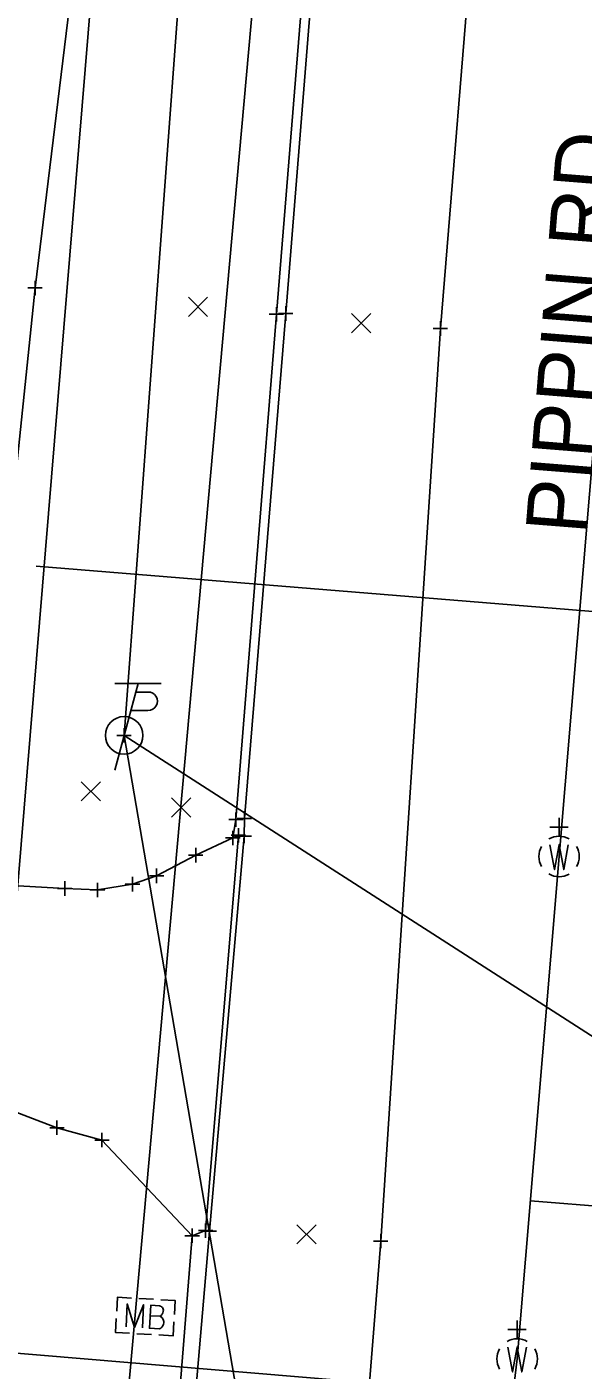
# Model space of a CAD drawing. Extents: x 1380440 to 1381945, y 468756 to 470369.
# Drawn here: x 1381508.5 to 1381547.1, y 469159.2 to 469252.2 of the extents above; entities that cross this region are included whole.
import ezdxf

# ---------------------------------------------------------------- set-up
doc = ezdxf.new("R2010")
doc.units = 0
for name, color, linetype in [('DR_X_Cells', 7, 'Continuous'), ('GE_P_Driveway_CL', 7, 'Continuous'), ('PM_X_CL_Double_Solid', 7, 'Continuous'), ('PV_X_COP', 7, 'Continuous'), ('RD_P_Cells', 7, 'Continuous'), ('RW_P_Const_Limits', 7, 'Continuous'), ('RW_P_Esmt_TMP', 7, 'Continuous'), ('RW_X_Esmt_SH', 7, 'Continuous'), ('SC_Scratch2', 7, 'Continuous'), ('SC_Shading1', 7, 'Continuous'), ('SH_Named_Boundary', 7, 'Continuous'), ('UT_X_Gas', 7, 'Continuous'), ('UT_X_Overhead_Combined', 7, 'Continuous'), ('UT_X_Sanitary_Line', 7, 'Continuous'), ('UT_X_Water', 7, 'Continuous'), ('X-CL', 7, 'Continuous'), ('X-SUBDIVISION', 7, 'Continuous')]:
    doc.layers.add(name, color=color, linetype=linetype)

msp = doc.modelspace()

# ---------------------------------------------------------------- linework, layer by layer
at = {"layer": 'DR_X_Cells'}
msp.add_lwpolyline([(1381528.617, 469268.06), (1381528.681, 469267.335), (1381525.826, 469232.259), (1381523.028, 469197.272), (1381522.806, 469196.001)], dxfattribs=at)
at = {"layer": 'GE_P_Driveway_CL'}
for p, q in [((1381519.728, 469232.108), (1381521.062, 469233.443)), ((1381519.728, 469233.443), (1381521.062, 469232.108)), ((1381531.026, 469230.976), (1381532.36, 469232.31)), ((1381531.026, 469232.31), (1381532.36, 469230.976)), ((1381512.301, 469198.557), (1381513.635, 469199.892)), ((1381512.301, 469199.892), (1381513.635, 469198.557)), ((1381518.558, 469197.448), (1381519.892, 469198.783)), ((1381518.558, 469198.783), (1381519.892, 469197.448)), ((1381527.245, 469167.888), (1381528.579, 469169.223)), ((1381527.245, 469169.223), (1381528.579, 469167.888))]:
    msp.add_line(p, q, dxfattribs=at)
at = {"layer": 'PM_X_CL_Double_Solid'}
msp.add_lwpolyline([(1381555.385, 469442.034), (1381550.974, 469391.016), (1381547.282, 469345.901), (1381541.953, 469289.547), (1381537.187, 469231.269), (1381533.052, 469168.087), (1381530.317, 469133.741), (1381523.968, 469065.081), (1381520.119, 469021.37), (1381518.183, 469001.306)], dxfattribs=at)
at = {"layer": 'PV_X_COP'}
for p, q in [((1381516.242, 469206.701), (1381514.636, 469200.701)), ((1381517.842, 469206.701), (1381514.642, 469206.701)), ((1381516.082, 469206.101), (1381516.932, 469206.101)), ((1381515.741, 469204.826), (1381516.932, 469204.826))]:
    msp.add_line(p, q, dxfattribs=at)
msp.add_circle((1381515.279, 469203.101), 1.3, dxfattribs=at)
msp.add_arc((1381516.945, 469205.463), 0.638, 268.8767, 91.1233, dxfattribs=at)
at = {"layer": 'RD_P_Cells'}
for p, q in [((1381516.306, 469164.114), (1381517.306, 469164.059)), ((1381516.749, 469162.866), (1381516.749, 469162.866)), ((1381516.17, 469161.675), (1381517.17, 469161.619))]:
    msp.add_line(p, q, dxfattribs=at)
for points in [[(1381514.766, 469163.229), (1381514.82, 469164.197), (1381515.788, 469164.143)], [(1381515.41, 469162.139), (1381515.499, 469163.737), (1381515.989, 469162.107), (1381516.631, 469163.674), (1381516.542, 469162.076)], [(1381517.773, 469162.879), (1381517.839, 469162.938), (1381517.879, 469162.974), (1381517.906, 469163.01), (1381517.92, 469163.034), (1381517.948, 469163.083), (1381517.963, 469163.12), (1381517.993, 469163.207), (1381517.995, 469163.245), (1381517.998, 469163.295), (1381517.99, 469163.371), (1381517.968, 469163.436), (1381517.933, 469163.488), (1381517.873, 469163.542), (1381517.824, 469163.57), (1381517.8, 469163.584), (1381517.738, 469163.612), (1381517.122, 469163.647), (1381517.033, 469162.049), (1381517.725, 469162.011), (1381517.815, 469162.056), (1381517.894, 469162.115), (1381517.963, 469162.212), (1381518.007, 469162.323), (1381518.026, 469162.436), (1381518.03, 469162.511), (1381518.009, 469162.588), (1381517.965, 469162.704), (1381517.906, 469162.783), (1381517.773, 469162.879), (1381517.081, 469162.917)], [(1381517.822, 469164.03), (1381518.814, 469163.975), (1381518.76, 469163.006)], [(1381515.653, 469161.704), (1381514.684, 469161.757), (1381514.738, 469162.726)], [(1381518.732, 469162.504), (1381518.678, 469161.535), (1381517.686, 469161.591)]]:
    msp.add_lwpolyline(points, dxfattribs=at)
at = {"layer": 'RW_P_Const_Limits'}
for p, q in [((1381545.409, 469196.113), (1381545.409, 469197.385)), ((1381546.044, 469196.75), (1381544.772, 469196.75)), ((1381545.409, 469194.713), (1381545.409, 469194.713)), ((1381543.139, 469161.964), (1381541.867, 469161.964)), ((1381542.504, 469161.327), (1381542.504, 469162.599)), ((1381542.504, 469159.927), (1381542.504, 469159.927))]:
    msp.add_line(p, q, dxfattribs=at)
for points in [[(1381544.772, 469195.533), (1381545.091, 469193.81), (1381545.409, 469195.533), (1381545.729, 469193.81), (1381546.046, 469195.533)], [(1381541.867, 469160.747), (1381542.186, 469159.024), (1381542.504, 469160.747), (1381542.824, 469159.024), (1381543.141, 469160.747)]]:
    msp.add_lwpolyline(points, dxfattribs=at)
for centre, start, end in [((1381545.409, 469194.715), 150.01836, 209.98164), ((1381545.409, 469194.715), 60.01836, 120.01574), ((1381545.409, 469194.715), 330.01836, 29.98164), ((1381545.409, 469194.715), 239.98426, 299.98164), ((1381542.504, 469159.929), 60.01836, 120.01574), ((1381542.504, 469159.929), 150.01836, 209.98164), ((1381542.504, 469159.929), 330.01836, 29.98164)]:
    msp.add_arc(centre, 1.4, start, end, dxfattribs=at)
at = {"layer": 'RW_P_Esmt_TMP'}
msp.add_lwpolyline([(1381529.296, 469267.435), (1381526.47, 469232.309), (1381523.61, 469197.346), (1381523.606, 469196.129), (1381521.185, 469168.775), (1381520.163, 469156.66), (1381518.942, 469140.358), (1381518.512, 469135.769), (1381515.95, 469110.139), (1381515.909, 469109.22), (1381513.991, 469088.497), (1381512.042, 469066.797), (1381509.955, 469044.61), (1381509.763, 469043.721), (1381507.936, 469023.869), (1381507.813, 469022.448), (1381506.018, 469002.556)], dxfattribs=at)
at = {"layer": 'RW_X_Esmt_SH'}
for points in [[(1381522.806, 469196.001), (1381520.236, 469194.807), (1381517.53, 469193.378), (1381515.859, 469192.799), (1381513.438, 469192.399), (1381511.168, 469192.502), (1381505.078, 469192.845), (1381496.323, 469193.936), (1381487.288, 469195.085), (1381469.577, 469197.418)], [(1381522.806, 469196.001), (1381523.194, 469196.184), (1381520.924, 469168.811), (1381519.994, 469168.458)], [(1381487.828, 469171.671), (1381488.593, 469175.573), (1381489.804, 469177.06), (1381491.802, 469178.459), (1381493.744, 469178.705), (1381499.999, 469178.744), (1381505.248, 469177.971), (1381510.629, 469175.939), (1381513.747, 469175.079), (1381519.994, 469168.458), (1381519.164, 469158.007), (1381519.539, 469157.132)]]:
    msp.add_lwpolyline(points, dxfattribs=at)
at = {"layer": 'SC_Scratch2'}
msp.add_lwpolyline([(1381512.834, 469264.598), (1381509.111, 469234.077), (1381505.616, 469200.413)], dxfattribs=at)
at = {"layer": 'SC_Shading1'}
msp.add_lwpolyline([(1381555.385, 469442.034), (1381550.974, 469391.016), (1381547.282, 469345.901), (1381541.953, 469289.547), (1381537.187, 469231.269), (1381533.052, 469168.087), (1381530.317, 469133.741), (1381523.968, 469065.081), (1381520.119, 469021.37), (1381518.183, 469001.306)], dxfattribs=at)
at = {"layer": 'SH_Named_Boundary'}
for p, q in [((1381509.111, 469234.577), (1381509.111, 469233.577)), ((1381508.611, 469234.077), (1381509.611, 469234.077)), ((1381509.111, 469234.077), (1381509.111, 469234.077)), ((1381525.826, 469232.759), (1381525.826, 469231.759)), ((1381526.47, 469232.809), (1381526.47, 469231.809)), ((1381525.326, 469232.259), (1381526.326, 469232.259)), ((1381525.826, 469232.259), (1381525.826, 469232.259)), ((1381525.97, 469232.309), (1381526.97, 469232.309)), ((1381526.47, 469232.309), (1381526.47, 469232.309)), ((1381537.187, 469231.769), (1381537.187, 469230.769)), ((1381536.687, 469231.269), (1381537.687, 469231.269)), ((1381537.187, 469231.269), (1381537.187, 469231.269)), ((1381515.279, 469203.601), (1381515.279, 469202.601)), ((1381515.279, 469203.601), (1381515.279, 469202.601)), ((1381515.279, 469203.601), (1381515.279, 469202.601)), ((1381515.279, 469203.601), (1381515.279, 469202.601)), ((1381514.779, 469203.101), (1381515.779, 469203.101)), ((1381514.779, 469203.101), (1381515.779, 469203.101)), ((1381514.779, 469203.101), (1381515.779, 469203.101)), ((1381514.779, 469203.101), (1381515.779, 469203.101)), ((1381515.279, 469203.101), (1381515.279, 469203.101)), ((1381515.279, 469203.101), (1381515.279, 469203.101)), ((1381515.279, 469203.101), (1381515.279, 469203.101)), ((1381515.279, 469203.101), (1381515.279, 469203.101)), ((1381522.528, 469197.272), (1381523.528, 469197.272)), ((1381523.028, 469197.772), (1381523.028, 469196.772)), ((1381523.028, 469197.272), (1381523.028, 469197.272)), ((1381523.11, 469197.346), (1381524.11, 469197.346)), ((1381523.61, 469197.846), (1381523.61, 469196.846)), ((1381523.61, 469197.346), (1381523.61, 469197.346)), ((1381522.694, 469196.184), (1381523.694, 469196.184)), ((1381522.806, 469196.501), (1381522.806, 469195.501)), ((1381522.806, 469196.501), (1381522.806, 469195.501)), ((1381522.806, 469196.501), (1381522.806, 469195.501)), ((1381523.194, 469196.684), (1381523.194, 469195.684)), ((1381523.194, 469196.184), (1381523.194, 469196.184)), ((1381523.606, 469196.629), (1381523.606, 469195.629)), ((1381520.236, 469195.307), (1381520.236, 469194.307)), ((1381522.306, 469196.001), (1381523.306, 469196.001)), ((1381522.306, 469196.001), (1381523.306, 469196.001)), ((1381522.306, 469196.001), (1381523.306, 469196.001)), ((1381522.806, 469196.001), (1381522.806, 469196.001)), ((1381522.806, 469196.001), (1381522.806, 469196.001)), ((1381522.806, 469196.001), (1381522.806, 469196.001)), ((1381523.106, 469196.129), (1381524.106, 469196.129)), ((1381523.606, 469196.129), (1381523.606, 469196.129)), ((1381519.736, 469194.807), (1381520.736, 469194.807)), ((1381520.236, 469194.807), (1381520.236, 469194.807)), ((1381517.03, 469193.378), (1381518.03, 469193.378)), ((1381517.53, 469193.878), (1381517.53, 469192.878)), ((1381517.53, 469193.378), (1381517.53, 469193.378)), ((1381510.668, 469192.502), (1381511.668, 469192.502)), ((1381511.168, 469193.002), (1381511.168, 469192.002)), ((1381511.168, 469192.502), (1381511.168, 469192.502)), ((1381513.438, 469192.899), (1381513.438, 469191.899)), ((1381515.359, 469192.799), (1381516.359, 469192.799)), ((1381515.859, 469193.299), (1381515.859, 469192.299)), ((1381515.859, 469192.799), (1381515.859, 469192.799)), ((1381512.938, 469192.399), (1381513.938, 469192.399)), ((1381513.438, 469192.399), (1381513.438, 469192.399)), ((1381510.129, 469175.939), (1381511.129, 469175.939)), ((1381510.629, 469176.439), (1381510.629, 469175.439)), ((1381510.629, 469175.939), (1381510.629, 469175.939)), ((1381513.247, 469175.079), (1381514.247, 469175.079)), ((1381513.747, 469175.579), (1381513.747, 469174.579)), ((1381513.747, 469175.079), (1381513.747, 469175.079)), ((1381520.924, 469169.311), (1381520.924, 469168.311)), ((1381521.185, 469169.275), (1381521.185, 469168.275)), ((1381519.494, 469168.458), (1381520.494, 469168.458)), ((1381519.494, 469168.458), (1381520.494, 469168.458)), ((1381519.994, 469168.958), (1381519.994, 469167.958)), ((1381519.994, 469168.958), (1381519.994, 469167.958)), ((1381519.994, 469168.458), (1381519.994, 469168.458)), ((1381519.994, 469168.458), (1381519.994, 469168.458)), ((1381520.424, 469168.811), (1381521.424, 469168.811)), ((1381520.685, 469168.775), (1381521.685, 469168.775)), ((1381520.924, 469168.811), (1381520.924, 469168.811)), ((1381521.185, 469168.775), (1381521.185, 469168.775)), ((1381533.052, 469168.587), (1381533.052, 469167.587)), ((1381532.552, 469168.087), (1381533.552, 469168.087)), ((1381533.052, 469168.087), (1381533.052, 469168.087))]:
    msp.add_line(p, q, dxfattribs=at)
at = {"layer": 'UT_X_Gas'}
msp.add_lwpolyline([(1381485.898, 468926.411), (1381594.271, 470237.893), (1380558.001, 470279.291)], dxfattribs=at)
at = {"layer": 'UT_X_Overhead_Combined'}
for points in [[(1381540.8, 469054.263), (1381515.279, 469203.101), (1381529.165, 469390.12), (1381543.86, 469565.781), (1381559.775, 469757.408), (1381571.968, 469887.64), (1381581.264, 470018.199), (1381595.795, 470220.833), (1381665.562, 470247.404)], [(1381515.279, 469203.101), (1381575.349, 469164.511)]]:
    msp.add_lwpolyline(points, dxfattribs=at)
at = {"layer": 'UT_X_Sanitary_Line'}
msp.add_line((1381558.175, 469210.835), (1381509.187, 469214.819), dxfattribs=at)
at = {"layer": 'UT_X_Water'}
for p, q in [((1381545.409, 469194.713), (1381630.263, 470209.692)), ((1381542.504, 469159.927), (1381545.409, 469194.713)), ((1381612.166, 469165.147), (1381543.419, 469170.882)), ((1381542.208, 469157.439), (1381472.466, 469163.312)), ((1381527.445, 469033.396), (1381542.504, 469159.927))]:
    msp.add_line(p, q, dxfattribs=at)
at = {"layer": 'X-CL'}
msp.add_line((1381528.037, 469296.447), (1381500.707, 468992.415), dxfattribs=at)

# ---------------------------------------------------------------- texts
at = {"layer": 'X-SUBDIVISION'}
msp.add_text('PIPPIN RD.', height=4.1667, rotation=85.44278, dxfattribs=at).set_placement((1381547.236, 469216.961))

doc.saveas('drawing.dxf')
